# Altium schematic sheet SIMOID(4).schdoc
size 420 x 297 mm; Symbol: Drawing-Symbol_A4; @Project Name: Inverted_MAML_6x6; @Page Count: 1; @Update Date: 2026-06-14; @Create Date: 2026-06-14; @Schematic Name: Schematic1; @Page No: 1; @Page Name: P1; Company: EasyEDA.com; Version: V1.0; Page Size: A4; Device: Drawing-Symbol_A4; @Create Time: 16:51:10; @Update Time: 16:51:10; Border: 1; Width: 1655; Height: 1170; Region Start: 1; X Region Count: 6; Y Region Count: 4; Blade Width: 10; Title Block Position: 3
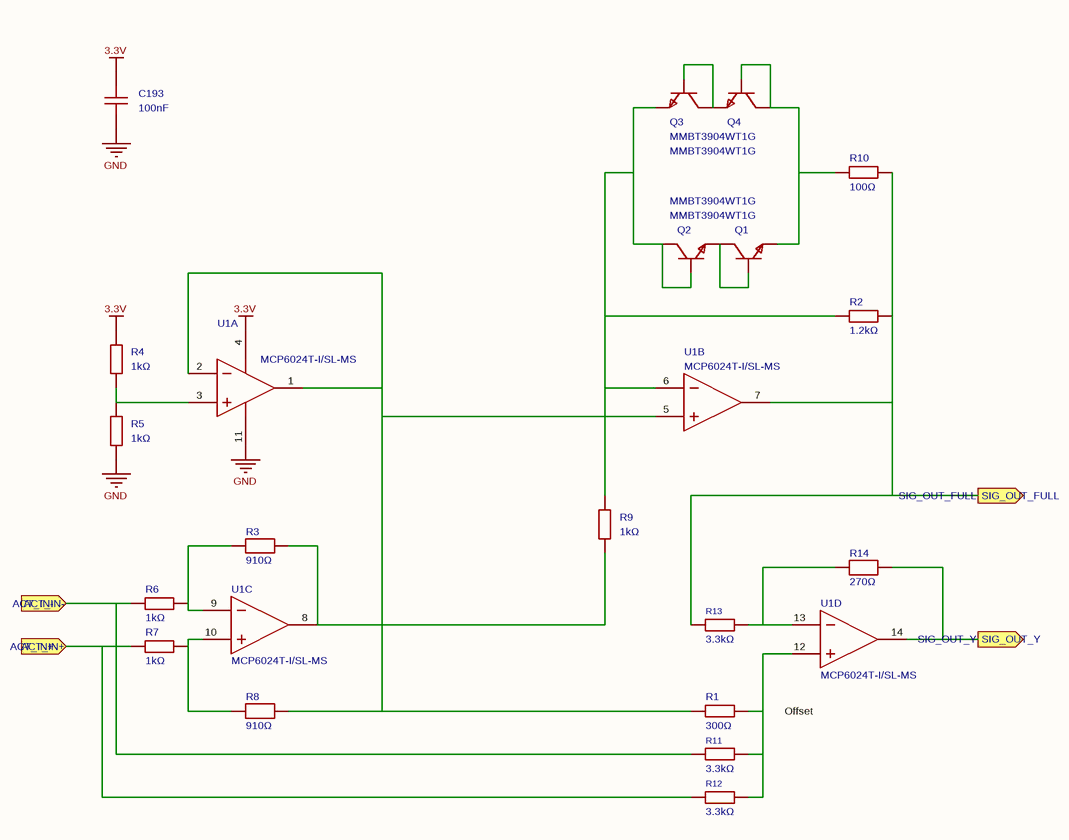
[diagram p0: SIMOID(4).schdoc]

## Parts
C193  100nF  [C0402]
Q1  MMBT3904WT1G  [SC-70-3_L2.1-W1.3-P1.30-LS2.1-BR]
Q2  MMBT3904WT1G  [SC-70-3_L2.1-W1.3-P1.30-LS2.1-BR]
Q3  MMBT3904WT1G  [SC-70-3_L2.1-W1.3-P1.30-LS2.1-BR]
Q4  MMBT3904WT1G  [SC-70-3_L2.1-W1.3-P1.30-LS2.1-BR]
R1  300Ω  [R0402]
R2  1.2kΩ  [R0402]
R3  910Ω  [R0402]
R4  1kΩ  [R0402]
R5  1kΩ  [R0402]
R6  1kΩ  [R0402]
R7  1kΩ  [R0402]
R8  910Ω  [R0402]
R9  1kΩ  [R0402]
R10  100Ω  [R0402]
R11  3.3kΩ  [R0402]
R12  3.3kΩ  [R0402]
R13  3.3kΩ  [R0402]
R14  270Ω  [R0402]
U1  MCP6024T-I/SL-MS  [SOIC-14_L8.7-W3.9-P1.27-LS6.0-BL-1]  (parts A,B,C,D of 4)

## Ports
ACT_IN+ (in), ACT_IN- (in), SIG_OUT_FULL (out), SIG_OUT_Y (out)

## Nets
3.3V: C193.2 R4.2 U1.4(V+)
GND: C193.1 R5.1 U1.11(V-)
ACT_IN+: R7.2 R12.1 ; port ACT_IN+
ACT_IN-: R6.2 R11.1 ; port ACT_IN-
SIG_OUT_FULL: R2.2 R10.1 R13.1 U1.7(OUT2) ; port SIG_OUT_FULL
SIG_OUT_Y: R14.2 U1.14(OUT4) ; port SIG_OUT_Y
NetQ1_1: Q1.1(B) Q1.3(C) Q2.2(E)
NetQ1_2: Q1.2(E) Q4.1(B) Q4.3(C) R10.2
NetQ2_1: Q2.1(B) Q2.3(C) Q3.2(E) R2.1 R9.1 U1.6(IN2-)
NetQ3_1: Q3.1(B) Q3.3(C) Q4.2(E)
NetR1_1: R1.1 R8.2 U1.1(OUT1) U1.2(IN1-) U1.5(IN2+)
NetR1_2: R1.2 R11.2 R12.2 U1.12(IN4+)
NetR3_1: R3.1 R6.1 U1.9(IN3-)
NetR3_2: R3.2 R9.2 U1.8(OUT3)
NetR4_1: R4.1 R5.2 U1.3(IN1+)
NetR7_1: R7.1 R8.1 U1.10(IN3+)
NetR13_2: R13.2 R14.1 U1.13(IN4-)

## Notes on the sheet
- Offset

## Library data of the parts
C193 = CL05B104KO5NNNC: Capacitance:100nF Tolerance:±10% Tolerance:±10% Voltage Rating:16V Temperature Coefficient:X7R; Manufacturer: SAMSUNG(三星); 3D Model: b7d13df3e9464d7a99d0651d1a5b4d570819f05c4eef4c71ace90d822a990e87; 3D Model Transform: 39.37,19.685,0,0,0,0,0,0,0; Tolerance: ±10%; Voltage Rating: 16V; Temperature Coefficient: X7R; AddInBom: yes; ModelName: C0402_L1.0-W0.5-H0.5
Q1-Q4 = MMBT3904WT1G: type:NPN Current - Collector(Ic):200mA Collector - Emitter Voltage VCEO:40V Pd - Power Dissipation:150mW DC Current Gain:40@0.1mA,1.0V DC Current Gain:40@0.1mA,1.0V Transition frequency(fT):300MHz Current - Collector Cutoff:50nA Vce Saturation(VCE(sat)):2; Manufacturer: onsemi(安森美); 3D Model: 13e0912de9fe4b51b1f46985f9be7482; 3D Model Transform: 82.677,78.74,0,180,0,0,-0.0025,0,0; type: NPN; Current - Collector(Ic): 200mA; Collector - Emitter Voltage VCEO: 40V; Pd - Power Dissipation: 150mW; Transition frequency(fT): 300MHz; Current - Collector Cutoff: 50nA; Vce Saturation(VCE(sat)): 200mV; Emitter-Base Voltage(Vebo): 6V; AddInBom: yes; ModelName: SC-70-3_L2.0-W1.3-H1.0-P0.65
R1 = 0402WGF3000TCE: Type:Thick Film Resistors Resistance: Tolerance:±1% Tolerance:±1% Power(Watts): Overload Voltage (Max): Temperature Coefficient:±100ppm/℃ Temperature Coefficient:±100ppm/℃ Operating Temperature Range:-55℃~+155℃ Operating Temperature Range:-55℃~+155℃; Manufacturer: UNI-ROYAL(厚声); AddInBom: yes; ModelId: efdecb7dae4442949d28eecaf748420f0819f05c4eef4c71ace90d822a990e87; ModelName: R0402_L1.0-W0.5-H0.4; ModelTransform: 39.37,19.685,0,0,0,0,0,0,0; Tolerance: ±1%
R2 = 0402WGF1201TCE: Type:Thick Film Resistor Resistance:1.2kΩ Tolerance:±1% Tolerance:±1% Power(Watts):62.5mW Voltage-Supply(Max):50V Temperature Coefficient:±100ppm/℃ Temperature Coefficient:±100ppm/℃ Operating Temperature:-55℃~+155℃ Operating Temperature:-55℃~+155℃; Manufacturer: UNI-ROYAL(厚声); AddInBom: yes; ModelId: efdecb7dae4442949d28eecaf748420f0819f05c4eef4c71ace90d822a990e87; ModelName: R0402_L1.0-W0.5-H0.4; ModelTransform: 39.37,19.685,0,0,0,0,0,0,0; Tolerance: ±1%; Power(Watts): 62.5mW; Voltage-Supply(Max): 50V
R3 R8 = SCR0402J910R: Type:Thick Film Resistor Resistance:910Ω Tolerance:±5% Tolerance:±5% Power(Watts):62.5mW Voltage-Supply(Max):50V Temperature Coefficient:±200ppm/℃ Temperature Coefficient:±200ppm/℃ Operating Temperature:-55℃~+155℃ Operating Temperature:-55℃~+155℃; Manufacturer: VO(翔胜); AddInBom: yes; ModelId: efdecb7dae4442949d28eecaf748420f0819f05c4eef4c71ace90d822a990e87; ModelName: R0402_L1.0-W0.5-H0.4; ModelTransform: 39.37,19.685,0,0,0,0,0,0,0; Tolerance: ±5%; Power(Watts): 62.5mW; Voltage-Supply(Max): 50V
R4-R7 R9 = 0402WGF1001TCE: Type:Thick Film Resistor Resistance:1kΩ Tolerance:±1% Tolerance:±1% Power(Watts):62.5mW Voltage-Supply(Max):50V Temperature Coefficient:±100ppm/℃ Temperature Coefficient:±100ppm/℃ Operating Temperature:-55℃~+155℃ Operating Temperature:-55℃~+155℃; Manufacturer: UNI-ROYAL(厚声); AddInBom: yes; ModelId: efdecb7dae4442949d28eecaf748420f0819f05c4eef4c71ace90d822a990e87; ModelName: R0402_L1.0-W0.5-H0.4; ModelTransform: 39.37,19.685,0,0,0,0,0,0,0; Tolerance: ±1%; Power(Watts): 62.5mW; Voltage-Supply(Max): 50V
R10 = 0402WGF1000TCE: Type:Thick Film Resistors Resistance: Tolerance:±1% Tolerance:±1% Power(Watts): Overload Voltage (Max): Temperature Coefficient:±200ppm/℃ Temperature Coefficient:±200ppm/℃ Operating Temperature Range:-55℃~+155℃ Operating Temperature Range:-55℃~+155℃; Manufacturer: UNI-ROYAL(厚声); 3D Model: efdecb7dae4442949d28eecaf748420f0819f05c4eef4c71ace90d822a990e87; 3D Model Transform: 39.37,19.685,0,0,0,0,0,0,0; Tolerance: ±1%; AddInBom: yes; ModelName: R0402_L1.0-W0.5-H0.4
R11-R13 = 0402WGF3301TCE: Type:Thick Film Resistor Resistance:3.3kΩ Tolerance:±1% Tolerance:±1% Power(Watts):62.5mW Voltage-Supply(Max):50V Temperature Coefficient:±100ppm/℃ Temperature Coefficient:±100ppm/℃ Operating Temperature:-55℃~+155℃ Operating Temperature:-55℃~+155℃; Manufacturer: UNI-ROYAL(厚声); AddInBom: yes; ModelId: efdecb7dae4442949d28eecaf748420f0819f05c4eef4c71ace90d822a990e87; ModelName: R0402_L1.0-W0.5-H0.4; ModelTransform: 39.37,19.685,0,0,0,0,0,0,0; Tolerance: ±1%; Power(Watts): 62.5mW; Voltage-Supply(Max): 50V
R14 = CRCW0402270RFKED: Type:Thick Film Resistors Resistance: Tolerance:±1% Tolerance:±1% Power(Watts): Overload Voltage (Max): Temperature Coefficient:±100ppm/℃ Temperature Coefficient:±100ppm/℃ Operating Temperature Range:-55℃~+155℃ Operating Temperature Range:-55℃~+155℃; Manufacturer: VISHAY(威世); AddInBom: yes; ModelId: efdecb7dae4442949d28eecaf748420f0819f05c4eef4c71ace90d822a990e87; ModelName: R0402_L1.0-W0.5-H0.4; ModelTransform: 39.37,19.685,0,0,0,0,0,0,0; Tolerance: ±1%
U1 = MCP6024T-I/SL-MS: Manufacturer: MSKSEMI(美森科); Relevance: []; AddInBom: yes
